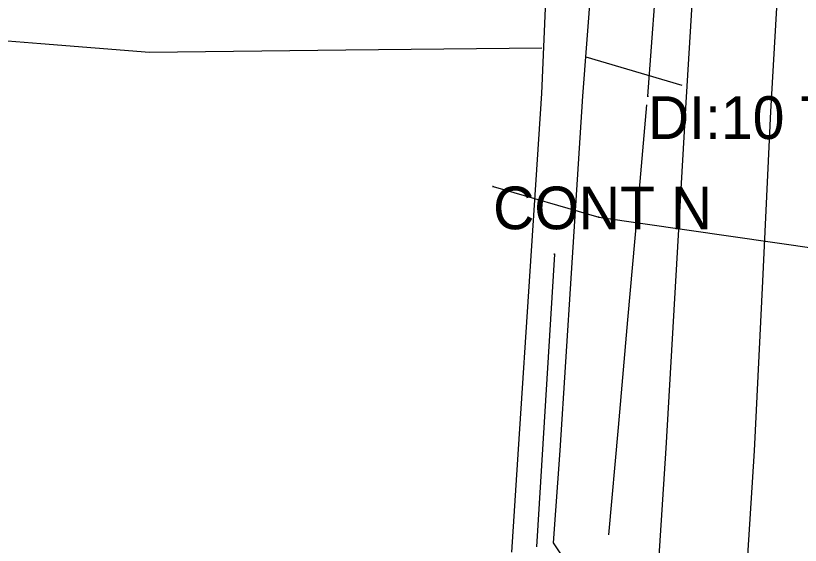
# Model space of a CAD drawing. Extents: x 997398 to 1003416, y 334596 to 337085.
# Drawn here: x 999156 to 999247.8, y 335281.4 to 335343.4 of the extents above; entities that cross this region are included whole.
import ezdxf

# ---------------------------------------------------------------- set-up
doc = ezdxf.new("R2010")
doc.units = 0
for name, color, linetype in [('S_DITCHLINE', 7, 'Continuous'), ('S_DRG_PT_SYM', 7, 'Continuous'), ('S_DRIVEWAY', 7, 'Continuous'), ('S_EDGE_PAVEMENT', 7, 'Continuous'), ('S_GAS_UTILITIES', 7, 'Continuous'), ('S_GAS_UTILITIES_ANNOT', 7, 'Continuous'), ('S_PAVEMENT_CROWN', 7, 'Continuous'), ('S_SIDE_DRAIN', 7, 'Continuous'), ('S_SIDE_DRAIN_ANNOT', 7, 'Continuous'), ('S_SIDEWALK', 7, 'Continuous'), ('S_UTL_PT_SYM', 7, 'Continuous')]:
    doc.layers.add(name, color=color, linetype=linetype)

msp = doc.modelspace()

# ---------------------------------------------------------------- linework, layer by layer
at = {"layer": 'S_DITCHLINE'}
msp.add_lwpolyline([(999225.366, 335282.578), (999226.476, 335295.175), (999227.586, 335307.772), (999228.697, 335320.369), (999229.807, 335332.966)], dxfattribs=at)
at = {"layer": 'S_DRG_PT_SYM'}
msp.add_lwpolyline([(999229.928, 335333.952), (999229.928, 335334.002), (999229.928, 335333.952), (999229.878, 335333.952), (999229.928, 335333.952), (999229.928, 335333.902), (999229.928, 335333.952), (999229.978, 335333.952)], dxfattribs=at)
at = {"layer": 'S_DRIVEWAY'}
for points in [[(999146.183, 335341.129), (999158.912, 335340.124), (999171.64, 335339.119), (999194.591, 335339.382), (999217.543, 335339.644)], [(999233.936, 335335.225), (999222.715, 335338.515)]]:
    msp.add_lwpolyline(points, dxfattribs=at)
at = {"layer": 'S_EDGE_PAVEMENT'}
msp.add_lwpolyline([(999231.226, 335279.525), (999232.055, 335292.74), (999233.228, 335312.984), (999234.401, 335333.228), (999235.908, 335357.547), (999237.415, 335381.866), (999238.413, 335402.401), (999239.41, 335422.936), (999240.427, 335440.217), (999241.444, 335457.499), (999242.461, 335474.78), (999243.478, 335492.061)], dxfattribs=at)
at = {"layer": 'S_GAS_UTILITIES'}
for p, q in [((999211.821, 335323.381), (999224.188, 335319.8)), ((999224.188, 335319.8), (999250.945, 335315.928)), ((999218.997, 335315.466), (999216.891, 335281.182))]:
    msp.add_line(p, q, dxfattribs=at)
at = {"layer": 'S_PAVEMENT_CROWN'}
msp.add_lwpolyline([(999240.929, 335269.145), (999242.42, 335292.445), (999243.36, 335312.306), (999244.3, 335332.168), (999245.733, 335356.524), (999247.166, 335380.881), (999248.328, 335401.353), (999249.491, 335421.826), (999250.518, 335439.547), (999251.544, 335457.269), (999252.571, 335474.99), (999253.598, 335492.711), (999255.463, 335505.528), (999257.328, 335518.345), (999259.194, 335531.162), (999261.059, 335543.979), (999262.924, 335556.796), (999264.789, 335569.613), (999266.655, 335582.43), (999268.52, 335595.247), (999272.871, 335613.495), (999277.221, 335631.744), (999281.766, 335646.204)], dxfattribs=at)
at = {"layer": 'S_SIDE_DRAIN'}
msp.add_line((999229.928, 335333.952), (999233.265, 335379.894), dxfattribs=at)
at = {"layer": 'S_SIDEWALK'}
for points in [[(999214.008, 335280.579), (999214.804, 335292.622), (999216.16, 335313.459), (999217.516, 335334.296), (999218.075, 335347.06), (999218.634, 335359.823), (999222.208, 335371.881), (999225.781, 335383.938), (999224.201, 335403.899), (999222.62, 335423.859), (999222.832, 335441.351), (999223.044, 335458.842), (999223.255, 335476.333), (999223.467, 335493.824), (999224.419, 335507.611), (999225.371, 335521.397), (999226.323, 335535.184), (999227.274, 335548.97)], [(999225.729, 335271.383), (999218.889, 335281.675), (999219.658, 335292.478), (999220.982, 335313.224), (999222.306, 335333.971), (999223.297, 335346.786), (999224.288, 335359.601), (999230.636, 335383.76), (999229.052, 335404.127), (999227.469, 335424.495), (999227.667, 335441.741), (999227.864, 335458.987), (999228.061, 335476.233), (999228.258, 335493.48), (999229.218, 335507.165), (999230.178, 335520.85), (999231.138, 335534.535), (999232.098, 335548.221)]]:
    msp.add_lwpolyline(points, dxfattribs=at)
at = {"layer": 'S_UTL_PT_SYM'}
for points in [[(999211.821, 335323.381), (999211.821, 335323.431), (999211.821, 335323.381), (999211.77, 335323.381), (999211.821, 335323.381), (999211.821, 335323.331), (999211.821, 335323.381), (999211.871, 335323.381)], [(999224.188, 335319.8), (999224.188, 335319.85), (999224.188, 335319.8), (999224.138, 335319.8), (999224.188, 335319.8), (999224.188, 335319.75), (999224.188, 335319.8), (999224.238, 335319.8)], [(999218.997, 335315.466), (999218.997, 335315.516), (999218.997, 335315.466), (999218.947, 335315.466), (999218.997, 335315.466), (999218.997, 335315.416), (999218.997, 335315.466), (999219.047, 335315.466)]]:
    msp.add_lwpolyline(points, dxfattribs=at)

# ---------------------------------------------------------------- texts
at = {"layer": 'S_GAS_UTILITIES_ANNOT'}
msp.add_text('CONT N', height=5, dxfattribs=at).set_placement((999211.821, 335318.381))
at = {"layer": 'S_SIDE_DRAIN_ANNOT'}
msp.add_text('DI:10 TY:RCP CN:90% FILL', height=5, dxfattribs=at).set_placement((999229.928, 335328.952))

doc.saveas('drawing.dxf')
